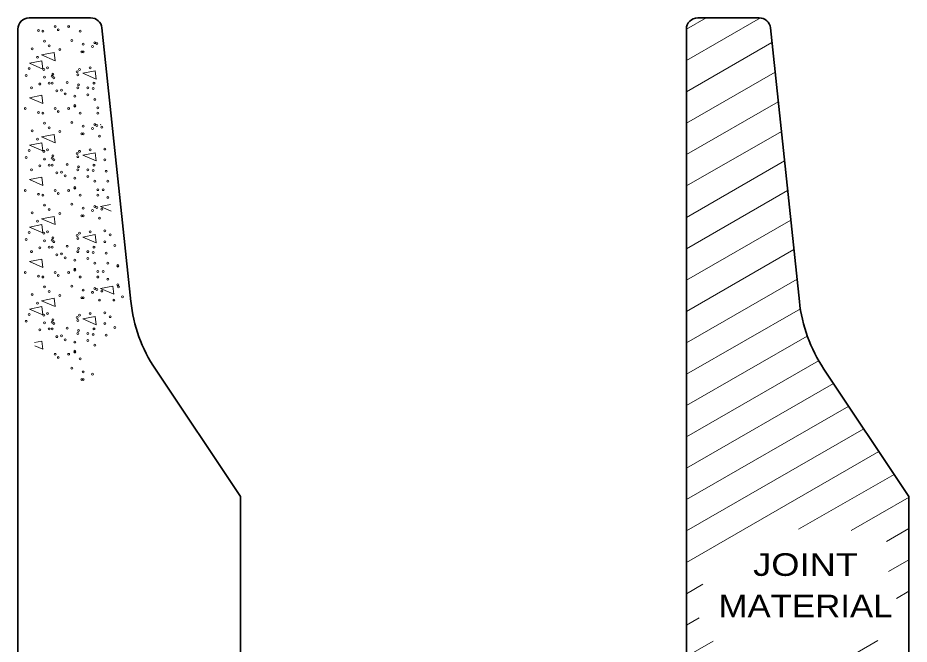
# Model space of a CAD drawing. Extents: x -43.06 to -36.2, y -1.41 to 7.25.
# Drawn here: x -38.826 to -36.463, y 5.585 to 7.247 of the extents above; entities that cross this region are included whole.
import ezdxf
from ezdxf.enums import TextEntityAlignment as Align

# ---------------------------------------------------------------- set-up
doc = ezdxf.new("R2010")
doc.units = 0
doc.header["$LTSCALE"] = 0.024
for name, color, linetype, lineweight in [('1', 7, 'Continuous', 35), ('12', 7, 'Continuous', 53), ('6', 7, 'Continuous', 13)]:
    doc.layers.add(name, color=color, linetype=linetype, lineweight=lineweight)

msp = doc.modelspace()

# ---------------------------------------------------------------- linework, layer by layer
at = {"layer": '1'}
for p, q in [((-38.79642, 7.247), (-38.63342, 7.247)), ((-37.02342, 7.247), (-36.86042, 7.247)), ((-38.60342, 7.22017), (-38.52675, 6.49483)), ((-36.83058, 7.22017), (-36.75375, 6.49483))]:
    msp.add_line(p, q, dxfattribs=at)
for points in [[(-38.82642, 7.217), (-38.82642, 5.49683), (-38.82642, 4.33667)], [(-37.05342, 7.217), (-37.05342, 5.49683), (-37.05342, 4.33667), (-37.13258, 3.58917)], [(-38.46175, 6.31517), (-38.23625, 5.97683), (-38.23625, 5.49683)], [(-36.68875, 6.31517), (-36.46325, 5.97683), (-36.46325, 5.49683), (-36.46325, 4.33667)]]:
    msp.add_lwpolyline(points, dxfattribs=at)
for centre, radius, start, end in [((-38.79636, 7.21707), 0.03001, 90, 180), ((-38.63333, 7.21707), 0.03001, 6.04438, 90), ((-37.0234, 7.21707), 0.03001, 90, 180), ((-36.86036, 7.21707), 0.03001, 6.04438, 90), ((-38.12884, 6.53699), 0.40006, 186.04451, 213.68755), ((-36.35588, 6.53699), 0.40006, 186.04451, 213.68755)]:
    msp.add_arc(centre, radius, start, end, dxfattribs=at)
at = {"layer": '6'}
for p, q in [((-37.05342, 7.217), (-37.00125, 7.247)), ((-37.05342, 7.13383), (-36.85692, 7.24683)), ((-37.05342, 7.05067), (-36.82642, 7.18117)), ((-37.05342, 6.96733), (-36.81808, 7.10283)), ((-37.05342, 6.88417), (-36.80975, 7.02433)), ((-38.60758, 6.96367), (-38.60625, 6.964)), ((-38.60625, 6.963), (-38.60758, 6.96367)), ((-37.05342, 6.801), (-36.80142, 6.94583)), ((-37.05342, 6.71767), (-36.79308, 6.8675)), ((-37.05342, 6.6345), (-36.78492, 6.789)), ((-38.60758, 6.74633), (-38.58092, 6.7515)), ((-38.57875, 6.734), (-38.60758, 6.74633)), ((-37.05342, 6.55117), (-36.77658, 6.7105)), ((-37.05342, 6.468), (-36.76825, 6.63217)), ((-37.05342, 6.38483), (-36.75992, 6.55367)), ((-37.05342, 6.3015), (-36.75108, 6.47533)), ((-37.05342, 6.21833), (-36.73275, 6.40283)), ((-37.05342, 6.13517), (-36.70308, 6.33667)), ((-37.05342, 6.05183), (-36.66308, 6.2765)), ((-37.05342, 5.96867), (-36.62292, 6.21633)), ((-37.05342, 5.8855), (-36.58275, 6.15617)), ((-37.05342, 5.80217), (-36.54275, 6.096)), ((-36.50258, 6.03583), (-36.75575, 5.89017)), ((-36.46258, 5.97567), (-36.61625, 5.88717)), ((-36.46325, 5.892), (-36.52242, 5.858)), ((-36.46325, 5.80867), (-36.51708, 5.77783)), ((-37.05342, 5.719), (-37.00992, 5.744)), ((-36.46325, 5.7255), (-36.49658, 5.70633)), ((-37.05342, 5.63567), (-37.01925, 5.6555)), ((-37.05342, 5.5525), (-36.98208, 5.5935)), ((-36.77958, 5.46033), (-36.54608, 5.59467))]:
    msp.add_line(p, q, dxfattribs=at)
for points in [[(-38.76325, 7.1485), (-38.73008, 7.155), (-38.72725, 7.133)], [(-38.79575, 7.1265), (-38.76275, 7.133), (-38.75992, 7.11117)], [(-38.65442, 7.10017), (-38.62125, 7.1065), (-38.61842, 7.08467)], [(-38.79575, 7.035), (-38.76275, 7.0415), (-38.75992, 7.0195)], [(-38.76325, 6.93117), (-38.73008, 6.93767), (-38.72725, 6.91567)], [(-38.79575, 6.90917), (-38.76275, 6.91567), (-38.75992, 6.89383)], [(-38.65442, 6.88267), (-38.62125, 6.88917), (-38.61842, 6.86733)], [(-38.79575, 6.81767), (-38.76275, 6.82417), (-38.75992, 6.80217)], [(-38.76325, 6.71383), (-38.73008, 6.72017), (-38.72725, 6.69833)], [(-38.79575, 6.69183), (-38.76275, 6.69833), (-38.75992, 6.6765)], [(-38.65442, 6.66533), (-38.62125, 6.67183), (-38.61842, 6.65)], [(-38.79575, 6.60033), (-38.76275, 6.60667), (-38.75992, 6.58483)], [(-38.60758, 6.529), (-38.57442, 6.5355), (-38.57158, 6.51367)], [(-38.76325, 6.49633), (-38.73008, 6.50283), (-38.72725, 6.481)], [(-38.79575, 6.4745), (-38.76275, 6.481), (-38.75992, 6.45917)], [(-38.65442, 6.448), (-38.62125, 6.4545), (-38.61842, 6.43267)]]:
    msp.add_lwpolyline(points, close=True, dxfattribs=at)
msp.add_lwpolyline([(-38.78258, 6.3855), (-38.76275, 6.38933), (-38.75992, 6.3675), (-38.78108, 6.37667)], dxfattribs=at)
for centre in [(-38.77196, 7.21351), (-38.75976, 7.21147), (-38.72715, 7.22371), (-38.71903, 7.21555), (-38.69159, 7.22371), (-38.66106, 7.21147), (-38.75568, 7.18503), (-38.68346, 7.18707), (-38.78824, 7.16467), (-38.74347, 7.17279), (-38.71495, 7.16262), (-38.65294, 7.17687), (-38.62849, 7.17079), (-38.62261, 7.18103), (-38.61697, 7.17859), (-38.774, 7.14226), (-38.65698, 7.1565), (-38.65294, 7.1565), (-38.74751, 7.11426), (-38.63462, 7.11426), (-38.80452, 7.09389), (-38.7964, 7.11222), (-38.75772, 7.11018), (-38.75568, 7.08981), (-38.73531, 7.09185), (-38.73327, 7.09797), (-38.66922, 7.10406), (-38.66718, 7.09593), (-38.6631, 7.11018), (-38.76788, 7.07149), (-38.74347, 7.07353), (-38.73531, 7.07353), (-38.73123, 7.08777), (-38.69567, 7.07557), (-38.66514, 7.06945), (-38.62441, 7.07353), (-38.79028, 7.06133), (-38.72311, 7.05317), (-38.71087, 7.05521), (-38.70071, 7.04505), (-38.66718, 7.06133), (-38.6407, 7.06133), (-38.6407, 7.04301), (-38.62645, 7.05929), (-38.6753, 7.03892), (-38.62237, 7.03076), (-38.80656, 7.00636), (-38.77196, 6.99616), (-38.72715, 7.00636), (-38.71903, 6.9982), (-38.69159, 7.00636), (-38.6753, 7.01448), (-38.6753, 7.01244), (-38.61425, 7.0084), (-38.75976, 6.99412), (-38.66106, 6.99412), (-38.61425, 6.99412), (-38.78824, 6.94731), (-38.75568, 6.96767), (-38.74347, 6.95543), (-38.68346, 6.96971), (-38.65294, 6.95951), (-38.62849, 6.95343), (-38.62261, 6.96367), (-38.61697, 6.96123), (-38.60333, 6.95687), (-38.774, 6.92491), (-38.71495, 6.94527), (-38.65698, 6.93915), (-38.65294, 6.93915), (-38.61017, 6.93307), (-38.80452, 6.87654), (-38.7964, 6.89486), (-38.75772, 6.89282), (-38.74751, 6.8969), (-38.73327, 6.88062), (-38.66922, 6.8867), (-38.66718, 6.87858), (-38.6631, 6.89282), (-38.63462, 6.8969), (-38.59593, 6.89894), (-38.76788, 6.85414), (-38.75568, 6.87246), (-38.74347, 6.85618), (-38.73531, 6.8745), (-38.73531, 6.85618), (-38.73123, 6.87042), (-38.69567, 6.85822), (-38.62441, 6.85618), (-38.59593, 6.87042), (-38.79028, 6.84397), (-38.72311, 6.83581), (-38.71087, 6.83785), (-38.66718, 6.84397), (-38.66514, 6.85209), (-38.6407, 6.84397), (-38.62645, 6.84193), (-38.59185, 6.83989), (-38.70071, 6.82769), (-38.6753, 6.82157), (-38.6407, 6.82565), (-38.62237, 6.81341), (-38.58777, 6.81341), (-38.80656, 6.789), (-38.72715, 6.789), (-38.69159, 6.789), (-38.6753, 6.79713), (-38.6753, 6.79509), (-38.61425, 6.79105), (-38.59997, 6.79105), (-38.77196, 6.7788), (-38.75976, 6.77676), (-38.71903, 6.78084), (-38.66106, 6.77676), (-38.61425, 6.77676), (-38.58777, 6.77068), (-38.75568, 6.75032), (-38.74347, 6.73808), (-38.68346, 6.75236), (-38.65294, 6.74216), (-38.62849, 6.73608), (-38.62261, 6.74632), (-38.61697, 6.74388), (-38.60333, 6.73952), (-38.78824, 6.72996), (-38.71495, 6.72792), (-38.65698, 6.72179), (-38.65294, 6.72179), (-38.61017, 6.71571), (-38.774, 6.70755), (-38.7964, 6.67751), (-38.75772, 6.67547), (-38.74751, 6.67955), (-38.66922, 6.66935), (-38.6631, 6.67547), (-38.63462, 6.67955), (-38.59593, 6.68159), (-38.58165, 6.67139), (-38.80452, 6.65918), (-38.75568, 6.6551), (-38.73531, 6.65714), (-38.73327, 6.66326), (-38.73123, 6.65306), (-38.69567, 6.64086), (-38.66718, 6.66122), (-38.59593, 6.65306), (-38.56945, 6.6429), (-38.79028, 6.62662), (-38.76788, 6.63678), (-38.74347, 6.63882), (-38.73531, 6.63882), (-38.72311, 6.61846), (-38.71087, 6.6205), (-38.66718, 6.62662), (-38.66514, 6.63474), (-38.6407, 6.62662), (-38.62645, 6.62458), (-38.62441, 6.63882), (-38.59185, 6.62254), (-38.70071, 6.61034), (-38.6753, 6.60422), (-38.6407, 6.6083), (-38.62237, 6.59605), (-38.58777, 6.59605), (-38.80656, 6.57165), (-38.72715, 6.57165), (-38.69159, 6.57165), (-38.6753, 6.57977), (-38.6753, 6.57773), (-38.61425, 6.57369), (-38.59997, 6.57369), (-38.56128, 6.58997), (-38.56128, 6.58793), (-38.77196, 6.56145), (-38.75976, 6.55941), (-38.71903, 6.56349), (-38.66106, 6.55941), (-38.61425, 6.55941), (-38.58777, 6.55333), (-38.75568, 6.53296), (-38.68346, 6.535), (-38.65294, 6.5248), (-38.62261, 6.52896), (-38.61697, 6.52652), (-38.60333, 6.52216), (-38.56128, 6.53904), (-38.55928, 6.53296), (-38.78824, 6.5126), (-38.74347, 6.52072), (-38.71495, 6.51056), (-38.65698, 6.50444), (-38.65294, 6.50444), (-38.62849, 6.51872), (-38.61017, 6.49836), (-38.57149, 6.49836), (-38.54908, 6.50648), (-38.774, 6.4902), (-38.7964, 6.46015), (-38.75772, 6.45811), (-38.74751, 6.46219), (-38.66922, 6.45199), (-38.6631, 6.45811), (-38.63462, 6.46219), (-38.59593, 6.46423), (-38.58165, 6.45403), (-38.80452, 6.44183), (-38.75568, 6.43775), (-38.73531, 6.43979), (-38.73327, 6.44591), (-38.73123, 6.43571), (-38.66718, 6.44387), (-38.59593, 6.43571), (-38.76788, 6.41943), (-38.74347, 6.42147), (-38.73531, 6.42147), (-38.69567, 6.42351), (-38.66718, 6.40926), (-38.66514, 6.41739), (-38.6407, 6.40926), (-38.62645, 6.40722), (-38.62441, 6.42147), (-38.59185, 6.40518), (-38.56945, 6.42555), (-38.72311, 6.4011), (-38.71087, 6.40314), (-38.70071, 6.39298), (-38.6753, 6.38686), (-38.6407, 6.39094), (-38.6753, 6.36242), (-38.6753, 6.36038), (-38.62237, 6.3787), (-38.72715, 6.3543), (-38.71903, 6.34613), (-38.69159, 6.3543), (-38.66106, 6.34205), (-38.68346, 6.31765), (-38.65698, 6.28708), (-38.65294, 6.30745), (-38.65294, 6.28708), (-38.62849, 6.30137)]:
    msp.add_circle(centre, 0.00252, dxfattribs=at)

# ---------------------------------------------------------------- texts
at = {"layer": '12'}
for s, width, p in [('JOINT', 1.2, (-36.73742, 5.76642)), ('MATERIAL', 1.15, (-36.73746, 5.65642))]:
    msp.add_text(s, height=0.06001, dxfattribs=dict(at, width=width)).set_placement(p, align=Align.CENTER)

doc.saveas('drawing.dxf')
